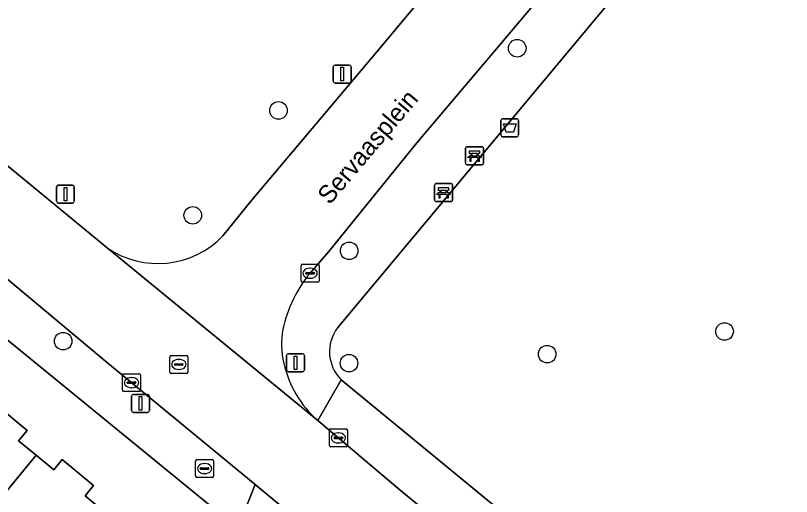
# Model space of a CAD drawing. Extents: x 162073 to 163043, y 381818 to 382561.
# Drawn here: x 162445.3 to 162488.5, y 381963.56 to 381990.33 of the extents above; entities that cross this region are included whole.
import ezdxf

# ---------------------------------------------------------------- set-up
doc = ezdxf.new("R2010")
doc.units = 0
for name, color, linetype in [('IMGEO_Afvalbak', 7, 'Continuous'), ('IMGEO_Bank', 7, 'Continuous'), ('IMGEO_Boom', 7, 'Continuous'), ('IMGEO_Brandkraan', 7, 'Continuous'), ('IMGEO_Erf', 7, 'Continuous'), ('IMGEO_Kolk', 7, 'Continuous'), ('IMGEO_Lichtmast', 7, 'Continuous'), ('IMGEO_Openbare_ruimte_label', 7, 'Continuous'), ('IMGEO_Pand', 7, 'Continuous'), ('IMGEO_Parkeervlak_open', 7, 'Continuous'), ('IMGEO_Rijbaan_lokaal_open', 7, 'Continuous'), ('IMGEO_Rioolput', 7, 'Continuous'), ('IMGEO_Voetpad_open', 7, 'Continuous')]:
    doc.layers.add(name, color=color, linetype=linetype)

msp = doc.modelspace()

# ---------------------------------------------------------------- linework, layer by layer
at = {"layer": 'IMGEO_Afvalbak'}
for p, q in [((162472.321, 381983.685), (162472.321, 381984.485)), ((162472.321, 381984.485), (162472.321, 381983.685)), ((162472.421, 381984.585), (162473.211, 381984.585)), ((162473.211, 381984.585), (162472.421, 381984.585)), ((162473.311, 381984.485), (162473.311, 381983.685)), ((162473.311, 381983.685), (162473.311, 381984.485)), ((162473.211, 381983.585), (162472.421, 381983.585)), ((162472.421, 381983.585), (162473.211, 381983.585))]:
    msp.add_line(p, q, dxfattribs=at)
msp.add_lwpolyline([(162472.464, 381984.299), (162473.168, 381984.299), (162473.019, 381983.829), (162472.613, 381983.829), (162472.464, 381984.299)], dxfattribs=at)
for centre, start, end in [((162472.421, 381984.485), 90, 180), ((162472.421, 381984.485), 90, 180), ((162473.211, 381984.485), 0, 90), ((162473.211, 381984.485), 360, 90), ((162472.421, 381983.685), 180, 270), ((162472.421, 381983.685), 180, 270), ((162473.211, 381983.685), 270, 0), ((162473.211, 381983.685), 270, 0)]:
    msp.add_arc(centre, 0.1, start, end, dxfattribs=at)
at = {"layer": 'IMGEO_Bank'}
for p, q in [((162470.435, 381983.026), (162471.276, 381983.026)), ((162471.276, 381983.026), (162470.435, 381983.026)), ((162470.36, 381982.101), (162470.36, 381982.942)), ((162470.36, 381982.942), (162470.36, 381982.101)), ((162470.669, 381982.532), (162470.669, 381982.638)), ((162470.713, 381982.638), (162470.713, 381982.532)), ((162471.001, 381982.644), (162470.719, 381982.644)), ((162471.007, 381982.532), (162471.007, 381982.638)), ((162471.051, 381982.638), (162471.051, 381982.532)), ((162471.36, 381982.951), (162471.36, 381982.11)), ((162471.36, 381982.11), (162471.36, 381982.951)), ((162471.057, 381982.424), (162470.664, 381982.424)), ((162470.719, 381982.526), (162471.001, 381982.526)), ((162471.285, 381982.026), (162470.444, 381982.026)), ((162470.444, 381982.026), (162471.285, 381982.026)), ((162468.636, 381980.049), (162468.636, 381980.89)), ((162468.636, 381980.89), (162468.636, 381980.049)), ((162468.711, 381980.974), (162469.552, 381980.974)), ((162469.552, 381980.974), (162468.711, 381980.974)), ((162469.636, 381980.899), (162469.636, 381980.058)), ((162469.636, 381980.058), (162469.636, 381980.899)), ((162469.333, 381980.372), (162468.94, 381980.372)), ((162468.945, 381980.48), (162468.945, 381980.586)), ((162468.989, 381980.586), (162468.989, 381980.48)), ((162469.277, 381980.592), (162468.995, 381980.592)), ((162468.995, 381980.474), (162469.277, 381980.474)), ((162469.283, 381980.48), (162469.283, 381980.586)), ((162469.327, 381980.586), (162469.327, 381980.48)), ((162469.561, 381979.974), (162468.72, 381979.974)), ((162468.72, 381979.974), (162469.561, 381979.974))]:
    msp.add_line(p, q, dxfattribs=at)
for points in [[(162470.663, 381982.644), (162470.577, 381982.644), (162470.577, 381982.805), (162471.14, 381982.805), (162471.14, 381982.644), (162471.057, 381982.644)], [(162470.607, 381982.424), (162470.465, 381982.424), (162470.577, 381982.526), (162470.663, 381982.526)], [(162470.657, 381982.417), (162470.657, 381982.21), (162470.614, 381982.21), (162470.614, 381982.417)], [(162471.057, 381982.526), (162471.14, 381982.526), (162471.252, 381982.424), (162471.113, 381982.424)], [(162471.107, 381982.417), (162471.107, 381982.21), (162471.063, 381982.21), (162471.063, 381982.417)], [(162468.883, 381980.372), (162468.741, 381980.372), (162468.853, 381980.474), (162468.939, 381980.474)], [(162468.939, 381980.592), (162468.853, 381980.592), (162468.853, 381980.753), (162469.416, 381980.753), (162469.416, 381980.592), (162469.333, 381980.592)], [(162469.333, 381980.474), (162469.416, 381980.474), (162469.528, 381980.372), (162469.389, 381980.372)], [(162468.933, 381980.365), (162468.933, 381980.158), (162468.89, 381980.158), (162468.89, 381980.365)], [(162469.383, 381980.365), (162469.383, 381980.158), (162469.339, 381980.158), (162469.339, 381980.365)]]:
    msp.add_lwpolyline(points, dxfattribs=at)
for centre, radius, start, end in [((162470.438, 381982.948), 0.0779, 92.4484, 184.2845), ((162470.438, 381982.948), 0.0779, 92.4484, 184.2845), ((162471.282, 381982.948), 0.0779, 2.4484, 94.2845), ((162471.282, 381982.948), 0.0779, 2.4484, 94.2845), ((162470.662, 381982.637), 0.00671, 2.8957, 87.1043), ((162470.662, 381982.533), 0.00671, 272.8957, 357.1043), ((162470.719, 381982.637), 0.00671, 92.8957, 177.1043), ((162470.719, 381982.533), 0.00671, 182.8957, 267.1043), ((162471.001, 381982.637), 0.00671, 2.8957, 87.1043), ((162471.001, 381982.533), 0.00671, 272.8957, 357.1043), ((162471.058, 381982.637), 0.00671, 92.8957, 177.1043), ((162471.058, 381982.533), 0.00671, 182.8957, 267.1043), ((162470.438, 381982.104), 0.0779, 182.4484, 274.2845), ((162470.438, 381982.104), 0.0779, 182.4484, 274.2845), ((162470.607, 381982.417), 0.00671, 2.8957, 87.1043), ((162470.664, 381982.417), 0.00671, 92.8957, 177.1043), ((162471.056, 381982.417), 0.00671, 2.8957, 87.1043), ((162471.113, 381982.417), 0.00671, 92.8957, 177.1043), ((162471.282, 381982.104), 0.0779, 272.4484, 4.2845), ((162471.282, 381982.104), 0.0779, 272.4484, 4.2845), ((162468.714, 381980.896), 0.0779, 92.4484, 184.2845), ((162468.714, 381980.896), 0.0779, 92.4484, 184.2845), ((162469.558, 381980.896), 0.0779, 2.4484, 94.2845), ((162469.558, 381980.896), 0.0779, 2.4484, 94.2845), ((162468.883, 381980.365), 0.00671, 2.8957, 87.1043), ((162468.94, 381980.365), 0.00671, 92.8957, 177.1043), ((162468.938, 381980.585), 0.00671, 2.8957, 87.1043), ((162468.938, 381980.481), 0.00671, 272.8957, 357.1043), ((162468.995, 381980.585), 0.00671, 92.8957, 177.1043), ((162468.995, 381980.481), 0.00671, 182.8957, 267.1043), ((162469.277, 381980.585), 0.00671, 2.8957, 87.1043), ((162469.277, 381980.481), 0.00671, 272.8957, 357.1043), ((162469.334, 381980.585), 0.00671, 92.8957, 177.1043), ((162469.334, 381980.481), 0.00671, 182.8957, 267.1043), ((162469.332, 381980.365), 0.00671, 2.8957, 87.1043), ((162469.389, 381980.365), 0.00671, 92.8957, 177.1043), ((162468.714, 381980.052), 0.0779, 182.4484, 274.2845), ((162468.714, 381980.052), 0.0779, 182.4484, 274.2845), ((162469.558, 381980.052), 0.0779, 272.4484, 4.2845), ((162469.558, 381980.052), 0.0779, 272.4484, 4.2845)]:
    msp.add_arc(centre, radius, start, end, dxfattribs=at)
at = {"layer": 'IMGEO_Boom'}
for centre in [(162473.235, 381988.507), (162459.942, 381985.048), (162455.171, 381979.212), (162463.876, 381977.232), (162484.778, 381972.745), (162447.954, 381972.205), (162474.904, 381971.484), (162463.869, 381970.984)]:
    msp.add_circle(centre, 0.489, dxfattribs=at)
at = {"layer": 'IMGEO_Brandkraan'}
for p, q in [((162455.331, 381964.691), (162455.331, 381965.543)), ((162455.406, 381965.617), (162456.258, 381965.617)), ((162455.819, 381965.397), (162455.844, 381965.397)), ((162456.332, 381965.543), (162456.332, 381964.691)), ((162455.59, 381965.111), (162455.59, 381965.123)), ((162456.028, 381965.074), (162455.63, 381965.074)), ((162455.633, 381965.16), (162456.031, 381965.16)), ((162455.842, 381964.837), (162455.817, 381964.837)), ((162456.074, 381965.123), (162456.074, 381965.111)), ((162456.258, 381964.617), (162455.406, 381964.617))]:
    msp.add_line(p, q, dxfattribs=at)
for points in [[(162455.331, 381964.691), (162455.331, 381965.543)], [(162455.406, 381965.617), (162456.258, 381965.617)], [(162456.332, 381965.543), (162456.332, 381964.691)], [(162456.258, 381964.617), (162455.406, 381964.617)]]:
    msp.add_lwpolyline(points, dxfattribs=at)
for centre, radius, start, end in [((162455.408, 381965.541), 0.0765, 91.552, 178.448), ((162455.408, 381965.541), 0.0765, 91.552, 178.448), ((162456.256, 381965.541), 0.0765, 1.552, 88.448), ((162456.256, 381965.541), 0.0765, 1.552, 88.448), ((162455.63, 381965.12), 0.0403, 85.8775, 175.7526), ((162455.627, 381965.11), 0.0366, 178.938, 274.7102), ((162456.031, 381965.117), 0.043, 264.8664, 352.4533), ((162456.035, 381965.122), 0.0386, 1.7309, 96.639), ((162455.408, 381964.693), 0.0765, 181.552, 268.448), ((162455.408, 381964.693), 0.0765, 181.552, 268.448), ((162456.256, 381964.693), 0.0765, 271.552, 358.448), ((162456.256, 381964.693), 0.0765, 271.552, 358.448)]:
    msp.add_arc(centre, radius, start, end, dxfattribs=at)
for centre, major_axis, ratio, start_param, end_param in [((162455.818, 381965.117), (-0.387, 0.002), 0.722429, 4.712389, 7.853982), ((162455.843, 381965.117), (-0.39, 0.002), 0.717154, 1.570796, 4.712389)]:
    msp.add_ellipse(centre, major_axis=major_axis, ratio=ratio, start_param=start_param, end_param=end_param, dxfattribs=at)
at = {"layer": 'IMGEO_Erf'}
for points in [[(162574.615, 382046.411), (162523.276, 382089.432), (162521.435, 382087.22), (162500, 382061.465), (162495.527, 382056.09), (162485.32, 382043.802), (162496.476, 382022.946), (162500, 382016.409), (162500.583, 382015.328), (162500.694, 382015.122), (162500, 382014.237), (162498.228, 382011.978), (162496.617, 382012.958), (162485.8, 382000), (162479.39, 381992.322), (162463.245, 381972.97)], [(162463.437, 381970.058), (162480.038, 381956.402), (162482.072, 381954.546)]]:
    msp.add_lwpolyline(points, dxfattribs=at)
msp.add_lwpolyline([(162439.099, 381976.949), (162433.232, 381969.849), (162434.415, 381968.865), (162437.834, 381972.975), (162438.976, 381972.025), (162439.455, 381972.599), (162441.141, 381971.197), (162440.646, 381970.602), (162443.626, 381968.123), (162444.138, 381968.738), (162445.942, 381967.238), (162445.468, 381966.668), (162446.447, 381965.854), (162447.427, 381965.039), (162447.905, 381965.613), (162449.644, 381964.166), (162449.173, 381963.6), (162452.162, 381961.113), (162452.656, 381961.706), (162454.42, 381960.239), (162453.947, 381959.671), (162455.127, 381958.689), (162457.681, 381961.808)], close=True, dxfattribs=at)
msp.add_arc((162464.985, 381971.622), 2.201, 142.2485, 225.296, dxfattribs=at)
at = {"layer": 'IMGEO_Kolk'}
for p, q in [((162461.276, 381976.488), (162462.128, 381976.488)), ((162461.201, 381975.562), (162461.201, 381976.414)), ((162461.689, 381976.268), (162461.714, 381976.268)), ((162462.202, 381976.414), (162462.202, 381975.562)), ((162461.46, 381975.982), (162461.46, 381975.994)), ((162461.898, 381975.945), (162461.5, 381975.945)), ((162461.503, 381976.031), (162461.901, 381976.031)), ((162461.712, 381975.708), (162461.687, 381975.708)), ((162461.944, 381975.994), (162461.944, 381975.982)), ((162462.128, 381975.488), (162461.276, 381975.488)), ((162451.262, 381969.472), (162451.262, 381970.324)), ((162451.337, 381970.398), (162452.189, 381970.398)), ((162451.75, 381970.178), (162451.775, 381970.178)), ((162452.263, 381970.324), (162452.263, 381969.472)), ((162451.521, 381969.892), (162451.521, 381969.904)), ((162451.959, 381969.855), (162451.561, 381969.855)), ((162451.564, 381969.941), (162451.962, 381969.941)), ((162451.773, 381969.618), (162451.748, 381969.618)), ((162452.005, 381969.904), (162452.005, 381969.892)), ((162452.189, 381969.398), (162451.337, 381969.398)), ((162462.776, 381966.397), (162462.776, 381967.249)), ((162462.851, 381967.323), (162463.703, 381967.323)), ((162463.264, 381967.103), (162463.289, 381967.103)), ((162463.777, 381967.249), (162463.777, 381966.397)), ((162463.035, 381966.817), (162463.035, 381966.829)), ((162463.473, 381966.78), (162463.075, 381966.78)), ((162463.078, 381966.866), (162463.476, 381966.866)), ((162463.287, 381966.543), (162463.262, 381966.543)), ((162463.519, 381966.829), (162463.519, 381966.817)), ((162463.703, 381966.323), (162462.851, 381966.323))]:
    msp.add_line(p, q, dxfattribs=at)
for points in [[(162461.276, 381976.488), (162462.128, 381976.488)], [(162461.201, 381975.562), (162461.201, 381976.414)], [(162462.202, 381976.414), (162462.202, 381975.562)], [(162462.128, 381975.488), (162461.276, 381975.488)], [(162451.262, 381969.472), (162451.262, 381970.324)], [(162451.337, 381970.398), (162452.189, 381970.398)], [(162452.263, 381970.324), (162452.263, 381969.472)], [(162452.189, 381969.398), (162451.337, 381969.398)], [(162462.776, 381966.397), (162462.776, 381967.249)], [(162462.851, 381967.323), (162463.703, 381967.323)], [(162463.777, 381967.249), (162463.777, 381966.397)], [(162463.703, 381966.323), (162462.851, 381966.323)]]:
    msp.add_lwpolyline(points, dxfattribs=at)
for centre, radius, start, end in [((162461.278, 381976.412), 0.0765, 91.552, 178.448), ((162461.278, 381976.412), 0.0765, 91.552, 178.448), ((162462.126, 381976.412), 0.0765, 1.552, 88.448), ((162462.126, 381976.412), 0.0765, 1.552, 88.448), ((162461.5, 381975.991), 0.0403, 85.8775, 175.7526), ((162461.497, 381975.981), 0.0366, 178.938, 274.7102), ((162461.901, 381975.988), 0.043, 264.8664, 352.4533), ((162461.905, 381975.993), 0.0386, 1.7309, 96.639), ((162461.278, 381975.564), 0.0765, 181.552, 268.448), ((162461.278, 381975.564), 0.0765, 181.552, 268.448), ((162462.126, 381975.564), 0.0765, 271.552, 358.448), ((162462.126, 381975.564), 0.0765, 271.552, 358.448), ((162451.339, 381970.322), 0.0765, 91.552, 178.448), ((162451.339, 381970.322), 0.0765, 91.552, 178.448), ((162452.187, 381970.322), 0.0765, 1.552, 88.448), ((162452.187, 381970.322), 0.0765, 1.552, 88.448), ((162451.561, 381969.901), 0.0403, 85.8775, 175.7526), ((162451.558, 381969.891), 0.0366, 178.938, 274.7102), ((162451.962, 381969.898), 0.043, 264.8664, 352.4533), ((162451.966, 381969.903), 0.0386, 1.7309, 96.639), ((162451.339, 381969.474), 0.0765, 181.552, 268.448), ((162451.339, 381969.474), 0.0765, 181.552, 268.448), ((162452.187, 381969.474), 0.0765, 271.552, 358.448), ((162452.187, 381969.474), 0.0765, 271.552, 358.448), ((162462.853, 381967.247), 0.0765, 91.552, 178.448), ((162462.853, 381967.247), 0.0765, 91.552, 178.448), ((162463.701, 381967.247), 0.0765, 1.552, 88.448), ((162463.701, 381967.247), 0.0765, 1.552, 88.448), ((162463.075, 381966.826), 0.0403, 85.8775, 175.7526), ((162463.072, 381966.816), 0.0366, 178.938, 274.7102), ((162463.476, 381966.823), 0.043, 264.8664, 352.4533), ((162463.48, 381966.828), 0.0386, 1.7309, 96.639), ((162462.853, 381966.399), 0.0765, 181.552, 268.448), ((162462.853, 381966.399), 0.0765, 181.552, 268.448), ((162463.701, 381966.399), 0.0765, 271.552, 358.448), ((162463.701, 381966.399), 0.0765, 271.552, 358.448)]:
    msp.add_arc(centre, radius, start, end, dxfattribs=at)
for centre, major_axis, ratio, start_param, end_param in [((162461.688, 381975.988), (-0.387, 0.002), 0.722429, 4.712389, 7.853982), ((162461.713, 381975.988), (-0.39, 0.002), 0.717154, 1.570796, 4.712389), ((162451.749, 381969.898), (-0.387, 0.002), 0.722429, 4.712389, 7.853982), ((162451.774, 381969.898), (-0.39, 0.002), 0.717154, 1.570796, 4.712389), ((162463.263, 381966.823), (-0.387, 0.002), 0.722429, 4.712389, 7.853982), ((162463.288, 381966.823), (-0.39, 0.002), 0.717154, 1.570796, 4.712389)]:
    msp.add_ellipse(centre, major_axis=major_axis, ratio=ratio, start_param=start_param, end_param=end_param, dxfattribs=at)
at = {"layer": 'IMGEO_Lichtmast'}
for p, q in [((162462.995, 381986.671), (162462.995, 381987.471)), ((162462.995, 381987.471), (162462.995, 381986.671)), ((162463.095, 381987.571), (162463.885, 381987.571)), ((162463.885, 381987.571), (162463.095, 381987.571)), ((162463.985, 381987.471), (162463.985, 381986.671)), ((162463.985, 381986.671), (162463.985, 381987.471)), ((162463.885, 381986.571), (162463.095, 381986.571)), ((162463.095, 381986.571), (162463.885, 381986.571)), ((162447.685, 381980.89), (162448.475, 381980.89)), ((162448.475, 381980.89), (162447.685, 381980.89)), ((162447.585, 381979.99), (162447.585, 381980.79)), ((162447.585, 381980.79), (162447.585, 381979.99)), ((162448.575, 381980.79), (162448.575, 381979.99)), ((162448.575, 381979.99), (162448.575, 381980.79)), ((162448.475, 381979.89), (162447.685, 381979.89)), ((162447.685, 381979.89), (162448.475, 381979.89)), ((162460.392, 381970.604), (162460.392, 381971.404)), ((162460.392, 381971.404), (162460.392, 381970.604)), ((162460.492, 381971.504), (162461.282, 381971.504)), ((162461.282, 381971.504), (162460.492, 381971.504)), ((162461.382, 381971.404), (162461.382, 381970.604)), ((162461.382, 381970.604), (162461.382, 381971.404)), ((162461.282, 381970.504), (162460.492, 381970.504)), ((162460.492, 381970.504), (162461.282, 381970.504)), ((162451.767, 381968.344), (162451.767, 381969.144)), ((162451.767, 381969.144), (162451.767, 381968.344)), ((162451.867, 381969.244), (162452.657, 381969.244)), ((162452.657, 381969.244), (162451.867, 381969.244)), ((162452.757, 381969.144), (162452.757, 381968.344)), ((162452.757, 381968.344), (162452.757, 381969.144)), ((162452.657, 381968.244), (162451.867, 381968.244)), ((162451.867, 381968.244), (162452.657, 381968.244))]:
    msp.add_line(p, q, dxfattribs=at)
for points in [[(162463.415, 381987.446), (162463.565, 381987.446), (162463.565, 381986.696), (162463.415, 381986.696), (162463.415, 381987.446)], [(162448.005, 381980.765), (162448.155, 381980.765), (162448.155, 381980.015), (162448.005, 381980.015), (162448.005, 381980.765)], [(162460.812, 381971.379), (162460.962, 381971.379), (162460.962, 381970.629), (162460.812, 381970.629), (162460.812, 381971.379)], [(162452.187, 381969.119), (162452.337, 381969.119), (162452.337, 381968.369), (162452.187, 381968.369), (162452.187, 381969.119)]]:
    msp.add_lwpolyline(points, dxfattribs=at)
for centre, start, end in [((162463.095, 381987.471), 90, 180), ((162463.095, 381987.471), 90, 180), ((162463.885, 381987.471), 0, 90), ((162463.885, 381987.471), 360, 90), ((162463.095, 381986.671), 180, 270), ((162463.095, 381986.671), 180, 270), ((162463.885, 381986.671), 270, 0), ((162463.885, 381986.671), 270, 0), ((162447.685, 381980.79), 90, 180), ((162447.685, 381980.79), 90, 180), ((162448.475, 381980.79), 0, 90), ((162448.475, 381980.79), 360, 90), ((162447.685, 381979.99), 180, 270), ((162447.685, 381979.99), 180, 270), ((162448.475, 381979.99), 270, 0), ((162448.475, 381979.99), 270, 0), ((162460.492, 381971.404), 90, 180), ((162460.492, 381971.404), 90, 180), ((162461.282, 381971.404), 0, 90), ((162461.282, 381971.404), 360, 90), ((162460.492, 381970.604), 180, 270), ((162460.492, 381970.604), 180, 270), ((162461.282, 381970.604), 270, 0), ((162461.282, 381970.604), 270, 0), ((162451.867, 381969.144), 90, 180), ((162451.867, 381969.144), 90, 180), ((162452.657, 381969.144), 0, 90), ((162452.657, 381969.144), 360, 90), ((162451.867, 381968.344), 180, 270), ((162451.867, 381968.344), 180, 270), ((162452.657, 381968.344), 270, 0), ((162452.657, 381968.344), 270, 0)]:
    msp.add_arc(centre, 0.1, start, end, dxfattribs=at)
at = {"layer": 'IMGEO_Pand'}
for points in [[(162440.468, 381958.617), (162446.447, 381965.854), (162445.468, 381966.668), (162445.942, 381967.238), (162444.138, 381968.738), (162443.626, 381968.123), (162440.646, 381970.602), (162441.141, 381971.197), (162439.455, 381972.599), (162438.976, 381972.025), (162437.834, 381972.975), (162434.415, 381968.865), (162433.232, 381969.849), (162430.956, 381967.113), (162431.162, 381966.941), (162434.654, 381964.038), (162433.235, 381962.332), (162436.887, 381959.295), (162438.018, 381960.655)], [(162440.468, 381958.617), (162442.902, 381956.592), (162441.763, 381955.223), (162445.331, 381952.255), (162446.549, 381953.719), (162449.175, 381951.535), (162451.93, 381954.846), (162455.127, 381958.689), (162453.947, 381959.671), (162454.42, 381960.239), (162452.656, 381961.706), (162452.162, 381961.113), (162449.173, 381963.6), (162449.644, 381964.166), (162447.905, 381965.613), (162447.427, 381965.039), (162446.447, 381965.854)]]:
    msp.add_lwpolyline(points, close=True, dxfattribs=at)
at = {"layer": 'IMGEO_Parkeervlak_open'}
for points in [[(162456.852, 381978.07), (162458.427, 381980.013), (162465.41, 381988.315), (162475.176, 382000), (162475.982, 382000.964), (162487.909, 382015.156)], [(162439.335, 381986.485), (162450.399, 381977.405)]]:
    msp.add_lwpolyline(points, dxfattribs=at)
msp.add_arc((162453.232, 381981.552), 5.023, 235.6605, 316.107, dxfattribs=at)
at = {"layer": 'IMGEO_Rijbaan_lokaal_open'}
for points in [[(162487.909, 382015.156), (162475.982, 382000.964), (162475.176, 382000), (162465.41, 381988.315), (162458.427, 381980.013), (162456.852, 381978.07)], [(162461.704, 381975.992), (162462.74, 381977.194), (162467.651, 381983.253), (162472.165, 381988.591), (162477.884, 381995.381)], [(162436.537, 381982.4), (162440.82, 381979.014), (162441.112, 381978.783), (162450.335, 381971.078), (162458.638, 381964.23), (162459.847, 381963.233), (162462.198, 381961.281), (162464.587, 381959.297), (162467.73, 381963.075), (162466.711, 381963.919), (162462.125, 381967.796), (162450.399, 381977.405), (162439.335, 381986.485)], [(162450.399, 381977.405), (162462.125, 381967.796)]]:
    msp.add_lwpolyline(points, dxfattribs=at)
for centre, radius, start, end in [((162453.232, 381981.552), 5.023, 235.6605, 316.107), ((162467.252, 381971.38), 7.214, 140.2638, 168.0837), ((162464.339, 381972.038), 4.229, 168.649, 194.6086), ((162466.041, 381972.255), 5.935, 192.4986, 228.7097)]:
    msp.add_arc(centre, radius, start, end, dxfattribs=at)
at = {"layer": 'IMGEO_Rioolput'}
for p, q in [((162453.897, 381970.486), (162453.897, 381971.338)), ((162453.972, 381971.412), (162454.824, 381971.412)), ((162454.898, 381971.338), (162454.898, 381970.486)), ((162454.156, 381970.906), (162454.156, 381970.918)), ((162454.594, 381970.869), (162454.196, 381970.869)), ((162454.199, 381970.955), (162454.597, 381970.955)), ((162454.385, 381971.192), (162454.41, 381971.192)), ((162454.64, 381970.918), (162454.64, 381970.906)), ((162454.408, 381970.632), (162454.383, 381970.632)), ((162454.824, 381970.412), (162453.972, 381970.412))]:
    msp.add_line(p, q, dxfattribs=at)
for points in [[(162453.897, 381970.486), (162453.897, 381971.338)], [(162453.972, 381971.412), (162454.824, 381971.412)], [(162454.898, 381971.338), (162454.898, 381970.486)], [(162454.824, 381970.412), (162453.972, 381970.412)]]:
    msp.add_lwpolyline(points, dxfattribs=at)
for centre, radius, start, end in [((162453.974, 381971.336), 0.0765, 91.552, 178.448), ((162453.974, 381971.336), 0.0765, 91.552, 178.448), ((162454.822, 381971.336), 0.0765, 1.552, 88.448), ((162454.822, 381971.336), 0.0765, 1.552, 88.448), ((162454.196, 381970.915), 0.0403, 85.8775, 175.7526), ((162454.193, 381970.905), 0.0366, 178.938, 274.7102), ((162454.597, 381970.912), 0.043, 264.8664, 352.4533), ((162454.601, 381970.917), 0.0386, 1.7309, 96.639), ((162453.974, 381970.488), 0.0765, 181.552, 268.448), ((162453.974, 381970.488), 0.0765, 181.552, 268.448), ((162454.822, 381970.488), 0.0765, 271.552, 358.448), ((162454.822, 381970.488), 0.0765, 271.552, 358.448)]:
    msp.add_arc(centre, radius, start, end, dxfattribs=at)
for centre, major_axis, ratio, start_param, end_param in [((162454.384, 381970.912), (-0.387, 0.002), 0.722429, 4.712389, 7.853982), ((162454.409, 381970.912), (-0.39, 0.002), 0.717154, 1.570796, 4.712389)]:
    msp.add_ellipse(centre, major_axis=major_axis, ratio=ratio, start_param=start_param, end_param=end_param, dxfattribs=at)
at = {"layer": 'IMGEO_Voetpad_open'}
for points in [[(162493.299, 382013.689), (162489.234, 382008.892), (162484.071, 382002.722), (162481.777, 382000), (162477.884, 381995.381), (162472.165, 381988.591), (162467.651, 381983.253), (162462.74, 381977.194), (162461.704, 381975.992)], [(162463.245, 381972.97), (162479.39, 381992.322)], [(162462.125, 381967.796), (162463.437, 381970.058)], [(162463.437, 381970.058), (162462.125, 381967.796), (162466.711, 381963.919), (162467.73, 381963.075), (162469.887, 381961.289), (162472.237, 381959.344), (162475.922, 381956.303)], [(162482.072, 381954.546), (162480.038, 381956.402), (162463.437, 381970.058)]]:
    msp.add_lwpolyline(points, dxfattribs=at)
for points in [[(162450.335, 381971.078), (162441.112, 381978.783), (162440.82, 381979.014), (162439.099, 381976.949), (162457.681, 381961.808), (162458.638, 381964.23)], [(162457.681, 381961.808), (162460.043, 381959.824), (162462.198, 381961.281), (162459.847, 381963.233), (162458.638, 381964.23)]]:
    msp.add_lwpolyline(points, close=True, dxfattribs=at)
for centre, radius, start, end in [((162467.252, 381971.38), 7.214, 140.2638, 168.0837), ((162464.339, 381972.038), 4.229, 168.649, 194.6086), ((162464.985, 381971.622), 2.201, 142.2485, 225.296), ((162466.041, 381972.255), 5.935, 192.4986, 228.7097)]:
    msp.add_arc(centre, radius, start, end, dxfattribs=at)

# ---------------------------------------------------------------- texts
at = {"layer": 'IMGEO_Openbare_ruimte_label'}
msp.add_text('Servaasplein', height=1, rotation=49.7838, dxfattribs=at).set_placement((162462.793, 381979.752))

doc.saveas('drawing.dxf')
